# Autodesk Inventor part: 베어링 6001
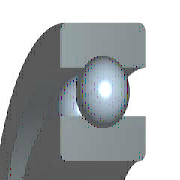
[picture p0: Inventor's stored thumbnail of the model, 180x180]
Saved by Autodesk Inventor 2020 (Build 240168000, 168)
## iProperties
Created: 2012-02
Part Number: 베어링 6001
Material: 강철, 연강
Description: 깊은 그루브 볼 베어링
Document SubType Name: Modeling
Standard: KS B 2023
Designer: mduedu
Standards Organization: KS
Language: ko-KR
Size Designation: 6001 - 12 x 28 x 8
Categories: <MemberInstance><Categories><Category DisplayName="샤프트 부품" InternalName="7f7aeb1f-a693-4053-b835-cee3144e0d98" Mnemonic="SHFT"><Category DisplayName="베어링" Inter
Density: 7.86 g/cm^3
Mass: 21.4854 g
Surface Area: 31.1809 cm^2
Volume: 2.73351 cm^3
Appearance: 노란색
IsCustomPart: 1
Author: mduedu
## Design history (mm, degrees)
sketch "스케치" dims "d0" = 4.16 (= -0.26 x WD + 0.26 x BD)
  geometry: L1 (1.92, 10)-(6.08, 10); L2 (4, 10)-(4, 7.92); L3 (4, 10)-(4, 12.08); L4 (2.454, 8.608)-(0, 8.608); L5 (0, 6)-(8, 6); L6 (2.454, 11.392)-(0, 11.392); L7 (0, 14)-(8, 14); L8 (8, 6)-(8, 8.608); L9 (5.546, 8.608)-(8, 8.608); L10 (5.546, 11.392)-(8, 11.392); L11 (8, 14)-(8, 11.392); L12 (-1.4, 0)-(8.4, 0) reference; L13 (0, -0.3)-(0, 5.3) reference
  constraints: 22 end point, 4 point on line, 2 collinear, 2 perpendicular, 2 symmetric about line, 1 midpoint, 1 parallel, 14 other
  dimensions: "d9" = 12 diameter of L5 L12 (= WD); "d11" = 28 diameter of L7 L12 (= BD); "d12" = 8 distance between parallel lines of L8 L13 (= KB); "d13" = 17.216 diameter of L9 L12 (= 0.326 x BD + 0.674 x WD)
revolve "본체" stored, may be unused: angle "d6" = 90 deg
revolve "볼" stored, may be unused: angle "d7" = 90 deg
pattern_circular "IDS_ARRAYBALL[SIMPL:T]" dims angle "d3" = 360 deg
body "Solid1"
fillet "모깎기1" dims "d1" = 0.3 (= KRS)
other parameters: "WD" = 12 [user parameter; used in 5 equation terms], "BD" = 28 [user parameter; used in 5 equation terms], "KB" = 8 [user parameter; used in 1 equation term], "KRS" = 0.3 [user parameter; used in 1 equation term], "d4" = 0, "d5" = 0, "d8" = 0, "d14" = 0, "d15" = 0, "BBA" = 0 [user parameter], "BC0" = 2360000 [user parameter], "BC" = 5070000 [user parameter], "BR" = 14 (= 0.5 x BD) [user parameter], "WR" = 6 (= 0.5 x WD) [user parameter]
